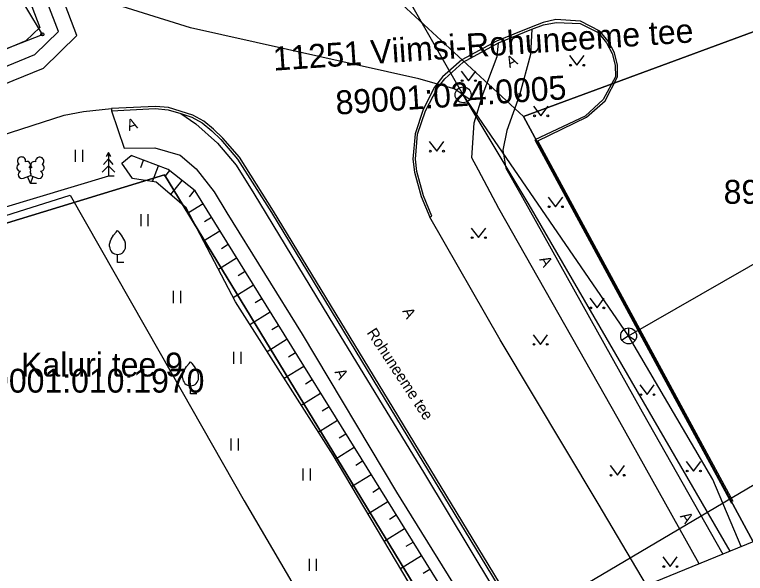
# Model space of a CAD drawing. Extents: x -52238384 to 549205, y 6582846 to 57187752.
# Drawn here: x 546520.53 to 546566.37, y 6597171.23 to 6597206.32 of the extents above; entities that cross this region are included whole.
import ezdxf

# ---------------------------------------------------------------- set-up
doc = ezdxf.new("R2010")
doc.units = 0
for name, color, linetype in [('kaluri tee mõõdistus$0$AED', 7, 'Continuous'), ('kaluri tee mõõdistus$0$HALJASTUS', 7, 'Continuous'), ('kaluri tee mõõdistus$0$KORGUS-EH2000', 7, 'Continuous'), ('kaluri tee mõõdistus$0$PUU', 7, 'Continuous'), ('kaluri tee mõõdistus$0$Reljeef', 7, 'Continuous'), ('kaluri tee mõõdistus$0$SIKAEV', 7, 'Continuous'), ('kaluri tee mõõdistus$0$SITRASS', 7, 'Continuous'), ('kaluri tee mõõdistus$0$TEE', 7, 'Continuous'), ('Kasutusala', 7, 'Continuous'), ('L_AADRESS', 7, 'Continuous'), ('Level 52', 7, 'Continuous'), ('Level 63', 7, 'Continuous'), ('PIIR', 7, 'Continuous'), ('TUNNUS', 7, 'Continuous')]:
    doc.layers.add(name, color=color, linetype=linetype)

# ---------------------------------------------------------------- blocks, each defined once
blk = doc.blocks.new('kaluri tee mõõdistus$0$MURU')
at = {"layer": 'kaluri tee mõõdistus$0$HALJASTUS'}
for p, q in [((-92.7, 121.3), (0, 0)), ((0, 0), (89.1, 121.3))]:
    blk.add_line(p, q, dxfattribs=at)
for centre in [(-80.2, 0), (85.5, 0)]:
    blk.add_circle(centre, 11, dxfattribs=at)
blk = doc.blocks.new('kaluri tee mõõdistus$0$HEIN')
at = {"layer": 'kaluri tee mõõdistus$0$HALJASTUS'}
for p, q in [((-45.5, 76.1), (-45.5, -76.1)), ((45.5, 76.1), (45.5, -76.1))]:
    blk.add_line(p, q, dxfattribs=at)
blk = doc.blocks.new('kaluri tee mõõdistus$0$SIKAEV')
at = {"layer": 'kaluri tee mõõdistus$0$SIKAEV'}
for p, q in [((0, 100), (0, 0)), ((0, 0), (-83, -55)), ((0, 0), (83, -55))]:
    blk.add_line(p, q, dxfattribs=at)
blk.add_circle((0, 0), 100, dxfattribs=at)
blk = doc.blocks.new('kaluri tee mõõdistus$0$LEHTP2')
at = {"layer": 'kaluri tee mõõdistus$0$PUU'}
for p, q in [((-88, 67), (1, 102)), ((1, 102), (89, 66)), ((0, 0), (-35, 88)), ((0, 0), (36, 88)), ((76, 0), (0, 0))]:
    blk.add_line(p, q, dxfattribs=at)
blk.add_lwpolyline([(1, 201), (-3, 186), (-3, 182), (-1, 176), (3, 169), (4, 165), (1, 158), (-4, 148), (-5, 143), (-4, 140), (-2, 134), (5, 122), (6, 118), (5, 114), (2, 107), (1, 102)], dxfattribs=at)
for centre, radius, start, end in [((-111.4, 282.8), 51.2, 111.50269, 232.51731), ((-111.4, 282.8), 51.2, 350.48556, 111.50017), ((-44.5, 232.7), 44.8, 308.50412, 111.57247), ((48.1, 231.8), 45, 67.7016, 230.51262), ((115.8, 281.1), 51.2, 67.6168, 188.63142), ((115.8, 281.1), 51.2, 306.59966, 67.61428), ((-126.2, 200.5), 44.8, 111.43041, 274.49868), ((0.8, 153.5), 47.5, 66.76552, 111.50149), ((129.3, 198.6), 44.8, 264.6183, 67.68657), ((-105.3, 111.7), 47.5, 111.50143, 291.50036), ((107, 110.1), 47.5, 247.61661, 67.61554)]:
    blk.add_arc(centre, radius, start, end, dxfattribs=at)
blk = doc.blocks.new('kaluri tee mõõdistus$0$RING02_1')
at = {"layer": 'kaluri tee mõõdistus$0$KORGUS-EH2000'}
blk.add_circle((0, 0), 20, dxfattribs=at)
blk = doc.blocks.new('kaluri tee mõõdistus$0$VILJA1')
at = {"layer": 'kaluri tee mõõdistus$0$PUU'}
for p, q in [((0, 0), (0, 100)), ((80, 0), (0, 0))]:
    blk.add_line(p, q, dxfattribs=at)
for points in [[(-100, 200), (-100, 230), (-98, 243), (-91, 269), (-79, 293), (-50, 340), (-18, 381), (0, 400)], [(100, 200), (100, 230), (98, 243), (91, 269), (79, 293), (50, 340), (18, 381), (0, 400)]]:
    blk.add_lwpolyline(points, dxfattribs=at)
blk.add_arc((0, 200), 100, 180, 0, dxfattribs=at)
blk = doc.blocks.new('kaluri tee mõõdistus$0$KUUSK1')
at = {"layer": 'kaluri tee mõõdistus$0$PUU'}
for p, q in [((0, 300), (-30, 250)), ((30, 250), (0, 300)), ((0, 300), (0, 0)), ((0, 220), (-60, 150)), ((60, 150), (0, 220)), ((0, 130), (-80, 50)), ((80, 50), (0, 130)), ((72, 0), (0, 0))]:
    blk.add_line(p, q, dxfattribs=at)

msp = doc.modelspace()

# ---------------------------------------------------------------- linework, layer by layer
at = {"layer": 'kaluri tee mõõdistus$0$AED'}
for points in [[(546488.135, 6597184.138), (546502.555, 6597188.204), (546524.017, 6597194.973)], [(546524.017, 6597194.973), (546529.648, 6597185.063), (546534.92, 6597175.789), (546538.987, 6597168.856), (546542.624, 6597165.497), (546543.03, 6597164.735)]]:
    msp.add_lwpolyline(points, dxfattribs=at)
at = {"layer": 'kaluri tee mõõdistus$0$HALJASTUS'}
msp.add_lwpolyline([(546526.412, 6597196.164), (546512.843, 6597192.092)], dxfattribs=at)
at = {"layer": 'kaluri tee mõõdistus$0$Reljeef'}
for p, q in [((546528.436, 6597196.716), (546528.613, 6597197.183)), ((546529.173, 6597195.839), (546529.548, 6597196.829)), ((546529.942, 6597196.131), (546530.254, 6597196.522)), ((546530.329, 6597195.012), (546531.036, 6597195.898)), ((546531.506, 6597194.884), (546531.818, 6597195.275)), ((546531.445, 6597193.888), (546532.345, 6597194.446)), ((546532.447, 6597193.333), (546532.872, 6597193.596)), ((546532.377, 6597192.113), (546533.399, 6597192.746)), ((546533.501, 6597191.633), (546533.926, 6597191.897)), ((546533.31, 6597190.338), (546534.453, 6597191.047)), ((546534.555, 6597189.933), (546534.98, 6597190.197)), ((546534.242, 6597188.562), (546535.507, 6597189.347)), ((546535.609, 6597188.234), (546536.034, 6597188.497)), ((546535.291, 6597186.86), (546536.561, 6597187.647)), ((546536.664, 6597186.534), (546537.088, 6597186.798)), ((546536.363, 6597185.171), (546537.616, 6597185.948)), ((546537.718, 6597184.834), (546538.143, 6597185.098)), ((546537.434, 6597183.482), (546538.67, 6597184.248)), ((546538.772, 6597183.135), (546539.197, 6597183.398)), ((546538.505, 6597181.793), (546539.724, 6597182.548)), ((546539.826, 6597181.435), (546540.251, 6597181.699)), ((546539.576, 6597180.104), (546540.778, 6597180.849)), ((546540.88, 6597179.735), (546541.305, 6597179.999)), ((546540.641, 6597178.41), (546541.832, 6597179.149)), ((546541.934, 6597178.036), (546542.359, 6597178.299)), ((546541.663, 6597176.691), (546542.886, 6597177.449)), ((546542.988, 6597176.336), (546543.413, 6597176.6)), ((546542.684, 6597174.971), (546543.94, 6597175.75)), ((546544.042, 6597174.636), (546544.467, 6597174.9)), ((546543.706, 6597173.251), (546544.994, 6597174.05)), ((546545.096, 6597172.937), (546545.521, 6597173.2)), ((546544.727, 6597171.531), (546546.048, 6597172.35)), ((546546.15, 6597171.237), (546546.575, 6597171.501))]:
    msp.add_line(p, q, dxfattribs=at)
for points in [[(546547.429, 6597167.465), (546545.608, 6597170.049), (546540.501, 6597178.646), (546534.391, 6597188.279), (546531.291, 6597194.181), (546529.414, 6597195.802), (546527.931, 6597196.029), (546527.243, 6597196.995), (546527.841, 6597197.476)], [(546548.199, 6597167.614), (546547.091, 6597170.669), (546531.844, 6597195.254), (546530.159, 6597196.597), (546527.841, 6597197.476)]]:
    msp.add_lwpolyline(points, dxfattribs=at)
at = {"layer": 'kaluri tee mõõdistus$0$SITRASS'}
for points in [[(546566.11, 6597172.916), (546564.327, 6597177.131), (546559.046, 6597186.14), (546548.663, 6597201.281), (546542.14, 6597212.709)], [(546548.663, 6597201.281), (546548.11, 6597201.65), (546545.89, 6597202.29), (546531.554, 6597205.491), (546522.056, 6597208.484), (546511.376, 6597210.741)], [(546565.424, 6597172.635), (546552.809, 6597194.377), (546548.663, 6597201.281)], [(546559.046, 6597186.14), (546578.686, 6597197.43)]]:
    msp.add_lwpolyline(points, dxfattribs=at)
at = {"layer": 'kaluri tee mõõdistus$0$TEE'}
for points in [[(546473.034, 6597193.848), (546473.679, 6597191.418), (546474.667, 6597190.222), (546475.266, 6597189.855), (546482.67, 6597192.141), (546485.882, 6597193.259), (546486.464, 6597193.742), (546486.212, 6597195.569), (546485.561, 6597197.791), (546488.008, 6597198.596), (546488.751, 6597195.981), (546489.598, 6597194.886), (546490.075, 6597194.545), (546495.577, 6597196.146), (546509.496, 6597200.439), (546517.764, 6597203.312), (546522.268, 6597205.075), (546521.293, 6597206.702), (546518.984, 6597210.646), (546513.99, 6597220.048), (546509.053, 6597229.628), (546508.194, 6597231.305)], [(546565.608, 6597175.738), (546553.359, 6597198.389), (546556.392, 6597199.875), (546557.575, 6597200.911), (546558.354, 6597202.405), (546558.336, 6597203.138), (546558.156, 6597203.927), (546557.777, 6597204.634), (546557.245, 6597205.272), (546556.015, 6597205.9), (546554.477, 6597206.003), (546553.693, 6597205.816), (546552.927, 6597205.529), (546550.762, 6597204.656), (546548.59, 6597203.482), (546547.379, 6597202.416), (546546.868, 6597201.767), (546546.153, 6597200.359), (546545.649, 6597198.832), (546545.499, 6597197.231), (546545.616, 6597196.416), (546546.022, 6597194.889), (546546.565, 6597193.6), (546546.698, 6597193.657)], [(546546.698, 6597193.657), (546546.175, 6597194.938), (546545.761, 6597196.471), (546545.668, 6597197.245), (546545.806, 6597198.805), (546546.305, 6597200.277), (546547.025, 6597201.681), (546547.525, 6597202.288), (546548.666, 6597203.338), (546550.881, 6597204.546), (546552.981, 6597205.413), (546553.696, 6597205.673), (546554.505, 6597205.831), (546555.997, 6597205.753), (546557.13, 6597205.186), (546557.647, 6597204.544), (546558.003, 6597203.874), (546558.194, 6597203.146), (546558.225, 6597202.4), (546557.457, 6597200.995), (546556.321, 6597199.946), (546553.151, 6597198.457), (546565.49, 6597175.637)], [(546552.981, 6597205.413), (546552.886, 6597203.812), (546552.196, 6597201.263), (546551.406, 6597199.039), (546551.146, 6597197.806), (546551.347, 6597196.666), (546552.283, 6597195.017), (546559.888, 6597181.375), (546564.962, 6597172.447)], [(546563.469, 6597171.835), (546558.392, 6597180.926), (546550.912, 6597194.132), (546549.62, 6597196.541), (546549.216, 6597197.322), (546549.35, 6597199.515), (546549.926, 6597201.37), (546550.791, 6597203.683), (546550.881, 6597204.546)], [(546474.304, 6597184.36), (546482.19, 6597186.874), (546482.631, 6597186.412), (546483.903, 6597184.826), (546484.329, 6597182.997), (546488.135, 6597184.138), (546487.344, 6597186.151), (546487.425, 6597187.304), (546488.091, 6597188.616), (546488.727, 6597188.923), (546497.087, 6597191.418), (546511.02, 6597195.812), (546519.628, 6597198.709), (546523.644, 6597200.01), (546524.855, 6597200.229), (546526.606, 6597200.416)], [(546550.953, 6597170.63), (546544.264, 6597181.617), (546536.776, 6597193.977), (546534.628, 6597197.363), (546533.595, 6597198.568), (546533.011, 6597199.133), (546532.4, 6597199.636), (546531.697, 6597200.012), (546530.175, 6597200.474), (546529.361, 6597200.552), (546526.606, 6597200.416), (546526.615, 6597200.271), (546529.353, 6597200.414), (546530.155, 6597200.335), (546530.963, 6597200.118), (546531.641, 6597199.88), (546532.285, 6597199.529), (546532.906, 6597199.027), (546533.455, 6597198.483), (546534.517, 6597197.247), (546536.649, 6597193.885), (546544.137, 6597181.535), (546550.806, 6597170.55)], [(546526.615, 6597200.271), (546527.402, 6597197.924), (546529.326, 6597197.959), (546530.918, 6597197.496), (546531.922, 6597196.632), (546533.05, 6597195.187), (546533.838, 6597193.867), (546538.561, 6597186.251), (546544.486, 6597176.327), (546548.644, 6597169.605), (546549.536, 6597168.055), (546550.026, 6597166.955)], [(546530.963, 6597200.118), (546531.905, 6597199.458), (546533.259, 6597198.255), (546534.424, 6597196.859), (546535.529, 6597195.075), (546540.236, 6597187.316), (546546.24, 6597177.49), (546550.51, 6597170.395), (546551.027, 6597169.59)], [(546560.175, 6597170.487), (546557.132, 6597175.616), (546550.987, 6597185.905), (546546.565, 6597193.6)], [(546583.191, 6597186.42), (546549.279, 6597166.35), (546488.139, 6597150.551)]]:
    msp.add_lwpolyline(points, dxfattribs=at)
at = {"layer": 'Kasutusala'}
msp.add_lwpolyline([(546524.436, 6597204.996), (546523.538, 6597207.384), (546522.64, 6597209.772), (546520.768, 6597209.068), (546521.436, 6597207.292), (546522.103, 6597205.516), (546521.227, 6597204.663), (546519.52, 6597203.964), (546517.813, 6597203.264), (546514.825, 6597202.225), (546511.837, 6597201.185), (546512.915, 6597198.64), (546515.76, 6597191.92), (546517.23, 6597192.37), (546515.859, 6597196.18), (546514.488, 6597199.99), (546516.505, 6597200.691), (546518.522, 6597201.393), (546520.433, 6597202.176), (546522.345, 6597202.96), (546523.39, 6597203.978)], close=True, dxfattribs=at)
at = {"layer": 'Level 52'}
msp.add_lwpolyline([(546556.701, 6597251.154), (546585.474, 6597180.84), (546491.483, 6597142.378), (546462.71, 6597212.692)], close=True, dxfattribs=at)
at = {"layer": 'Level 63'}
msp.add_lwpolyline([(546512.228, 6597200.262), (546518.168, 6597202.329), (546521.786, 6597203.811), (546523.27, 6597205.256), (546522.056, 6597208.484)], dxfattribs=at)
at = {"layer": 'PIIR'}
for points in [[(546524.023, 6597237.782), (546525.91, 6597233.41), (546537.23, 6597214.01), (546552.45, 6597199.91), (546566.856, 6597173.221)], [(546545.366, 6597164.427), (546544.44, 6597166.05), (546547.7, 6597167.01), (546529.93, 6597196.26), (546515.76, 6597191.92), (546510.07, 6597205.36), (546518.84, 6597207.6), (546506.3, 6597229.96), (546506.058, 6597230.431)], [(546574.352, 6597208.02), (546552.45, 6597199.91), (546537.23, 6597214.01), (546567.974, 6597223.606)], [(546566.856, 6597173.221), (546552.45, 6597199.91), (546574.352, 6597208.02)]]:
    msp.add_lwpolyline(points, dxfattribs=at)
msp.add_lwpolyline([(546529.93, 6597196.26), (546547.7, 6597167.01), (546544.44, 6597166.05), (546515.25, 6597157.51), (546505.65, 6597188.82), (546515.76, 6597191.92)], close=True, dxfattribs=at)

# ---------------------------------------------------------------- block references
at = {"layer": 'kaluri tee mõõdistus$0$HALJASTUS', "xscale": 0.005000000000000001, "yscale": 0.005000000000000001, "rotation": -4.073594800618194e-10}
for name, p in [('kaluri tee mõõdistus$0$MURU', (546555.802, 6597203.137)), ('kaluri tee mõõdistus$0$MURU', (546549.005, 6597202.167)), ('kaluri tee mõõdistus$0$MURU', (546553.545, 6597199.963)), ('kaluri tee mõõdistus$0$MURU', (546547.004, 6597197.742)), ('kaluri tee mõõdistus$0$HEIN', (546524.556, 6597197.454)), ('kaluri tee mõõdistus$0$MURU', (546554.462, 6597194.251)), ('kaluri tee mõõdistus$0$HEIN', (546528.664, 6597193.416)), ('kaluri tee mõõdistus$0$MURU', (546549.631, 6597192.311)), ('kaluri tee mõõdistus$0$HEIN', (546530.708, 6597188.584)), ('kaluri tee mõõdistus$0$MURU', (546557.068, 6597187.9)), ('kaluri tee mõõdistus$0$MURU', (546553.51, 6597185.611)), ('kaluri tee mõõdistus$0$HEIN', (546534.485, 6597184.759)), ('kaluri tee mõõdistus$0$MURU', (546560.21, 6597182.455)), ('kaluri tee mõõdistus$0$HEIN', (546534.315, 6597179.318)), ('kaluri tee mõõdistus$0$MURU', (546558.341, 6597177.394)), ('kaluri tee mõõdistus$0$MURU', (546563.119, 6597177.659)), ('kaluri tee mõõdistus$0$HEIN', (546538.838, 6597177.441)), ('kaluri tee mõõdistus$0$HEIN', (546539.226, 6597171.764)), ('kaluri tee mõõdistus$0$MURU', (546561.654, 6597171.657))]:
    msp.add_blockref(name, p, dxfattribs=at)
at = {"layer": 'kaluri tee mõõdistus$0$KORGUS-EH2000', "xscale": 0.005000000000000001, "yscale": 0.005000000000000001, "rotation": -4.073594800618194e-10}
for p in [(546522.268, 6597205.075), (546552.196, 6597201.263)]:
    msp.add_blockref('kaluri tee mõõdistus$0$RING02_1', p, dxfattribs=at)
at = {"layer": 'kaluri tee mõõdistus$0$PUU', "xscale": 0.005000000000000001, "yscale": 0.005000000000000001, "rotation": -4.073594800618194e-10}
for name, p in [('kaluri tee mõõdistus$0$KUUSK1', (546526.412, 6597196.164)), ('kaluri tee mõõdistus$0$LEHTP2', (546521.518, 6597195.709)), ('kaluri tee mõõdistus$0$VILJA1', (546526.988, 6597190.761)), ('kaluri tee mõõdistus$0$VILJA1', (546531.568, 6597182.511))]:
    msp.add_blockref(name, p, dxfattribs=at)
at = {"layer": 'kaluri tee mõõdistus$0$SIKAEV', "xscale": 0.005000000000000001, "yscale": 0.005000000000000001, "rotation": -4.073594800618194e-10}
for p in [(546548.663, 6597201.281), (546559.046, 6597186.14)]:
    msp.add_blockref('kaluri tee mõõdistus$0$SIKAEV', p, dxfattribs=at)

# ---------------------------------------------------------------- texts
at = {"layer": 'kaluri tee mõõdistus$0$TEE'}
for s, rotation, p in [('A', 26.8592, (546551.579, 6597202.952)), ('A', 18.7468, (546527.7, 6597199.001)), ('A', 298.0331, (546553.42, 6597190.95)), ('A', 298.0331, (546544.833, 6597187.705)), ('Rohuneeme tee', 303.3378, (546542.593, 6597186.343)), ('A', 298.0331, (546540.584, 6597183.879)), ('A', 303.2916, (546562.244, 6597174.815))]:
    msp.add_text(s, height=0.7, rotation=rotation, dxfattribs=at).set_placement(p)
at = {"layer": 'L_AADRESS'}
for s, rotation, p in [('11251 Viimsi-Rohuneeme tee', 3.8783, (546536.782, 6597202.794)), ('Kaluri tee 9', 360, (546520.938, 6597183.593))]:
    msp.add_text(s, height=1.5, rotation=rotation, dxfattribs=at).set_placement(p)
at = {"layer": 'TUNNUS'}
for s, rotation, p in [('89001:024:0005', 3.8783, (546540.712, 6597200.031)), ('89001:010:7310', 360, (546565.006, 6597194.438)), ('89001:010:1970', 360, (546517.935, 6597182.58))]:
    msp.add_text(s, height=1.5, rotation=rotation, dxfattribs=at).set_placement(p)

doc.saveas('drawing.dxf')
